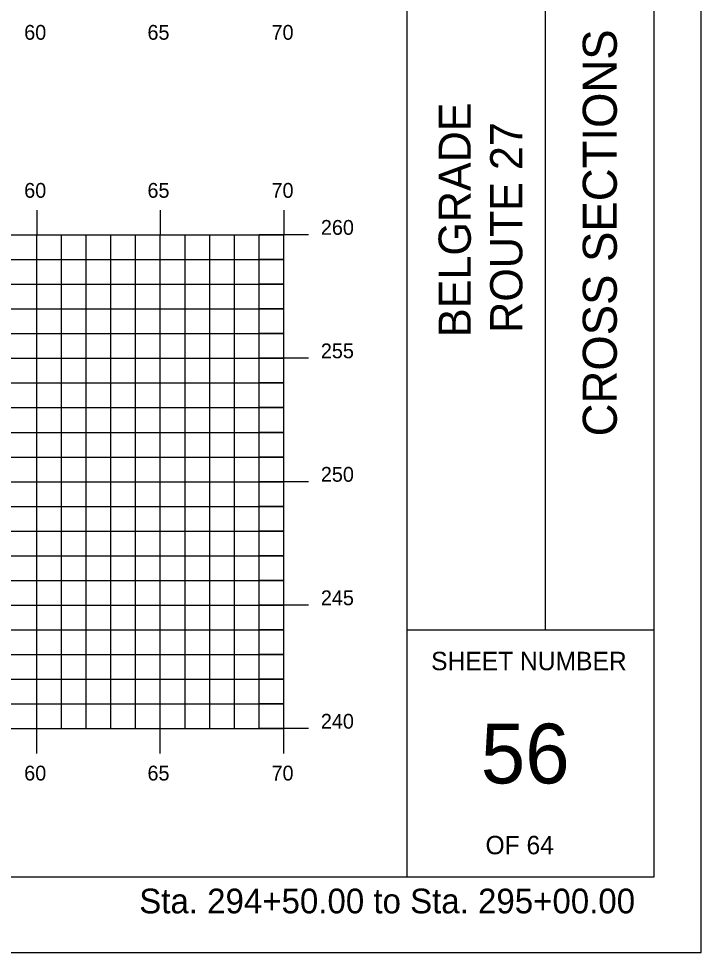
# Model space of a CAD drawing. Extents: x 859352 to 859522, y 366268 to 366378.
# Drawn here: x 859494.39 to 859522.04, y 366268.18 to 366305.99 of the extents above; entities that cross this region are included whole.
import ezdxf

# ---------------------------------------------------------------- set-up
doc = ezdxf.new("R2010")
doc.units = 0
for name, color, linetype in [('BORDER', 7, 'Continuous'), ('H_V ANNOTATION', 7, 'Continuous'), ('HIGHWAY_TITLE', 7, 'Continuous'), ('MAJOR', 7, 'Continuous'), ('MINOR', 7, 'Continuous'), ('PLOT BOUNDARY', 7, 'Continuous')]:
    doc.layers.add(name, color=color, linetype=linetype)

msp = doc.modelspace()

# ---------------------------------------------------------------- linework, layer by layer
at = {"layer": 'BORDER'}
for p, q in [((859510.13, 366271.236), (859510.13, 366376.239)), ((859520.13, 366271.236), (859520.13, 366376.236)), ((859515.721, 366281.239), (859515.721, 366316.239)), ((859510.13, 366281.239), (859520.13, 366281.239)), ((859360.13, 366271.236), (859520.13, 366271.236))]:
    msp.add_line(p, q, dxfattribs=at)
at = {"layer": 'MAJOR'}
for p, q in [((859495.129, 366298.238), (859495.129, 366297.236)), ((859500.129, 366298.238), (859500.129, 366297.236)), ((859505.129, 366298.238), (859505.129, 366297.236)), ((859365.129, 366297.236), (859505.129, 366297.236)), ((859365.129, 366297.236), (859505.129, 366297.236)), ((859495.129, 366277.236), (859495.129, 366297.236)), ((859500.129, 366277.236), (859500.129, 366297.236)), ((859506.131, 366297.236), (859504.127, 366297.236)), ((859505.129, 366277.236), (859505.129, 366297.236)), ((859505.129, 366277.236), (859505.129, 366297.236)), ((859365.129, 366292.236), (859505.129, 366292.236)), ((859506.131, 366292.236), (859504.127, 366292.236)), ((859365.129, 366287.236), (859505.129, 366287.236)), ((859506.131, 366287.236), (859504.127, 366287.236)), ((859365.129, 366282.236), (859505.129, 366282.236)), ((859506.131, 366282.236), (859504.127, 366282.236)), ((859365.129, 366277.236), (859505.129, 366277.236)), ((859365.129, 366277.236), (859505.129, 366277.236)), ((859495.129, 366276.234), (859495.129, 366277.236)), ((859500.129, 366276.234), (859500.129, 366277.236)), ((859506.131, 366277.236), (859504.127, 366277.236)), ((859505.129, 366276.234), (859505.129, 366277.236))]:
    msp.add_line(p, q, dxfattribs=at)
at = {"layer": 'MINOR'}
for p, q in [((859496.129, 366277.236), (859496.129, 366297.236)), ((859497.129, 366277.236), (859497.129, 366297.236)), ((859498.129, 366277.236), (859498.129, 366297.236)), ((859499.129, 366277.236), (859499.129, 366297.236)), ((859501.129, 366277.236), (859501.129, 366297.236)), ((859502.129, 366277.236), (859502.129, 366297.236)), ((859503.129, 366277.236), (859503.129, 366297.236)), ((859504.129, 366277.236), (859504.129, 366297.236)), ((859365.129, 366296.236), (859505.129, 366296.236)), ((859505.129, 366296.236), (859504.127, 366296.236)), ((859365.129, 366295.236), (859505.129, 366295.236)), ((859505.129, 366295.236), (859504.127, 366295.236)), ((859365.129, 366294.236), (859505.129, 366294.236)), ((859505.129, 366294.236), (859504.127, 366294.236)), ((859365.129, 366293.236), (859505.129, 366293.236)), ((859505.129, 366293.236), (859504.127, 366293.236)), ((859365.129, 366291.236), (859505.129, 366291.236)), ((859505.129, 366291.236), (859504.127, 366291.236)), ((859365.129, 366290.236), (859505.129, 366290.236)), ((859505.129, 366290.236), (859504.127, 366290.236)), ((859365.129, 366289.236), (859505.129, 366289.236)), ((859505.129, 366289.236), (859504.127, 366289.236)), ((859365.129, 366288.236), (859505.129, 366288.236)), ((859505.129, 366288.236), (859504.127, 366288.236)), ((859365.129, 366286.236), (859505.129, 366286.236)), ((859505.129, 366286.236), (859504.127, 366286.236)), ((859365.129, 366285.236), (859505.129, 366285.236)), ((859505.129, 366285.236), (859504.127, 366285.236)), ((859365.129, 366284.236), (859505.129, 366284.236)), ((859505.129, 366284.236), (859504.127, 366284.236)), ((859365.129, 366283.236), (859505.129, 366283.236)), ((859505.129, 366283.236), (859504.127, 366283.236)), ((859365.129, 366281.236), (859505.129, 366281.236)), ((859505.129, 366281.236), (859504.127, 366281.236)), ((859365.129, 366280.236), (859505.129, 366280.236)), ((859505.129, 366280.236), (859504.127, 366280.236)), ((859365.129, 366279.236), (859505.129, 366279.236)), ((859505.129, 366279.236), (859504.127, 366279.236)), ((859365.129, 366278.236), (859505.129, 366278.236)), ((859505.129, 366278.236), (859504.127, 366278.236))]:
    msp.add_line(p, q, dxfattribs=at)
at = {"layer": 'PLOT BOUNDARY'}
msp.add_lwpolyline([(859352.036, 366268.177), (859522.036, 366268.177), (859522.036, 366378.177), (859352.036, 366378.177)], close=True, dxfattribs=at)

# ---------------------------------------------------------------- texts
at = {"layer": 'BORDER'}
for s, height, rotation, p in [('CROSS SECTIONS', 1.37787, 90, (859518.614, 366289.073)), ('SHEET NUMBER', 0.74527, 360, (859511.095, 366279.603)), ('56', 2.4194, 360, (859513.105, 366275.019)), ('OF 64', 0.7453, 360, (859513.297, 366272.149))]:
    msp.add_text(s, height=height, rotation=rotation, dxfattribs=at).set_placement(p)
at = {"layer": 'H_V ANNOTATION'}
for s, height, p in [('60', 0.6, (859494.616, 366305.136)), ('65', 0.6, (859499.608, 366305.136)), ('70', 0.6, (859504.631, 366305.136)), ('60', 0.6, (859494.616, 366298.736)), ('65', 0.6, (859499.608, 366298.736)), ('70', 0.6, (859504.631, 366298.736)), ('260', 0.6, (859506.629, 366297.236)), ('255', 0.6, (859506.629, 366292.236)), ('250', 0.6, (859506.629, 366287.236)), ('245', 0.6, (859506.629, 366282.236)), ('240', 0.6, (859506.629, 366277.236)), ('60', 0.6, (859494.616, 366275.136)), ('65', 0.6, (859499.608, 366275.136)), ('70', 0.6, (859504.631, 366275.136)), ('Sta. 294+50.00 to Sta. 295+00.00', 1.0002, (859499.275, 366269.756))]:
    msp.add_text(s, height=height, dxfattribs=at).set_placement(p)
at = {"layer": 'HIGHWAY_TITLE'}
for s, p in [('BELGRADE', (859512.702, 366293.095)), ('ROUTE 27', (859514.789, 366293.269))]:
    msp.add_text(s, height=1.3043, rotation=90, dxfattribs=at).set_placement(p)

doc.saveas('drawing.dxf')
